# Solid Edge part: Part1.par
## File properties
Title: Index Feed
Author: Deepak Maini
Template: normal.par
Last saved by: Robert a Rhodes jr
Revision: 9
Application: Solid Edge
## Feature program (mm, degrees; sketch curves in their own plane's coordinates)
sketch for "unnamed Protrusion 1" plane through (0, 0, 0) normal (0, -1, 0) x-axis (1, 0, 0)
  line (-70.9604, 64.0839) -> (-70.9604, -73.7403)
  line (-70.9604, -73.7403) -> (54.0396, -73.7403)
  line (54.0396, -73.7403) -> (54.0396, -91.9161)
  line (54.0396, -91.9161) -> (129.0396, -91.9161)
  line (129.0396, -91.9161) -> (129.0396, -72.9161)
  line (129.0396, -72.9161) -> (254.0396, -72.9161)
  line (254.0396, -72.9161) -> (254.0396, 64.0839)
  line (254.0396, 64.0839) -> (-70.9604, 64.0839)
extrude "unnamed Protrusion 1" add finite 250 along -normal
sketch for "unnamed Cutout 1" plane through (-70.9604, 125, -4.8282) normal (-1, 0, 0) x-axis (0, -1, 0)
  line (-125, 14.6412) -> (-31, 68.9121)
  line (-30.1921, 85.7362) -> (-31, 68.9121)
  line (-156.4917, 85.7362) -> (-30.1921, 85.7362)
  line (-156.4917, 14.6412) -> (-156.4917, 85.7362)
  line (-125, 14.6412) -> (-156.4917, 14.6412)
  dimension (linear) = 125
extrude "unnamed Cutout 1" cut finite 290 along -normal
sketch for "unnamed Cutout 2" plane through (91.5396, 125, 64.0839) normal (0, 0, 1) x-axis (0, 1, 0)
  line (-125, 137.5) -> (86.3471, -37.5)
  line (-125, -194.3743) -> (-125, 137.5)
  line (125, -194.3743) -> (-125, -194.3743)
  line (125, -37.5) -> (125, -194.3743)
  line (125, -37.5) -> (87, -37.5)
extrude "unnamed Cutout 2" cut finite 62 along -normal
sketch for "unnamed Cutout 3" plane through (102.595, 125, 2.0839) normal (0, 0, 1) x-axis (0, 1, 0)
  line (-125, -51.4446) -> (-5.8246, -151.4446)
  line (-5.0536, -188.9251) -> (-5.8246, -151.4446)
  line (-164.4348, -188.9251) -> (-5.0536, -188.9251)
  line (-164.4348, -51.4446) -> (-164.4348, -188.9251)
  line (-125, -51.4446) -> (-164.4348, -51.4446)
extrude "unnamed Cutout 3" cut finite 19 along -normal
sketch for "unnamed Hole 1" plane through (102.595, 125, 2.0839) normal (0, 0, 1) x-axis (0, 1, 0)
  hole centre (-50, 10.5554) bore radius 25
hole "unnamed Hole 1" through
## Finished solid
Body 1: solid body, 19 faces, 46 edges, 28 vertices.
  Faces by surface: plane 17, cylinder 2
  Edges by curve: line 42, circle 4
Bounding box of the edges (mm): 325.000 x 250.000 x 156.000, from (-70.9604, 0, -91.9161) to (254.0396, 250, 64.0839).
Cylindrical faces by radius (mm): R25 x1, R37.5 x1
Planar faces by outward normal: +x 3, +y 1, +z 4, -x 2, -y 1, -z 3, oblique 3
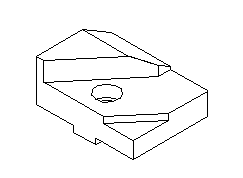
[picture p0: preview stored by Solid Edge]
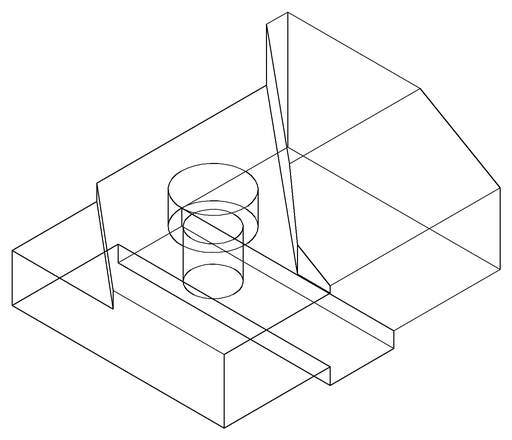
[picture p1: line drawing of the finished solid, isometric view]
